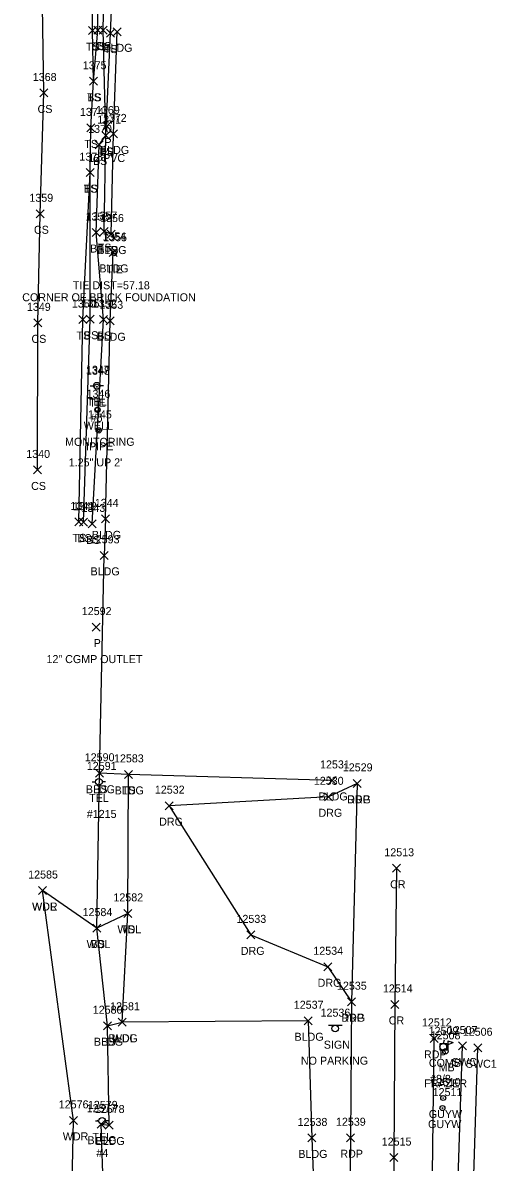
# Model space of a CAD drawing. Extents: x 1769141 to 1770817, y 735471 to 742405.
# Drawn here: x 1770172.1 to 1770290.5, y 741211.2 to 741496 of the extents above; entities that cross this region are included whole.
import ezdxf

# ---------------------------------------------------------------- set-up
doc = ezdxf.new("R2010")
doc.units = 0
for name, color, linetype in [('C_A', 7, 'Continuous'), ('C_C', 7, 'Continuous'), ('C_I', 7, 'Continuous'), ('CBP', 7, 'Continuous'), ('D_A', 7, 'Continuous'), ('D_C', 7, 'Continuous'), ('D_I', 7, 'Continuous'), ('D_TIC', 7, 'Continuous'), ('L_A', 7, 'Continuous'), ('L_C', 7, 'Continuous'), ('L_I', 7, 'Continuous'), ('L_TIC', 7, 'Continuous'), ('LAWA', 7, 'Continuous'), ('LBC', 7, 'Continuous'), ('LELB', 7, 'Continuous'), ('LMB', 7, 'Continuous'), ('M_A', 7, 'Continuous'), ('M_C', 7, 'Continuous'), ('M_I', 7, 'Continuous'), ('MPIP', 7, 'Continuous'), ('P_A', 7, 'Continuous'), ('P_I', 7, 'Continuous'), ('P_TIC', 7, 'Continuous'), ('PET', 7, 'Continuous'), ('PRC', 7, 'Continuous'), ('R_A', 7, 'Continuous'), ('R_I', 7, 'Continuous'), ('R_TIC', 7, 'Continuous'), ('RDG', 7, 'Continuous'), ('RSW', 7, 'Continuous'), ('S_A', 7, 'Continuous'), ('S_C', 7, 'Continuous'), ('S_I', 7, 'Continuous'), ('SSGN', 7, 'Continuous'), ('U_A', 7, 'Continuous'), ('U_C', 7, 'Continuous'), ('U_I', 7, 'Continuous'), ('UP', 7, 'Continuous'), ('UPGW', 7, 'Continuous'), ('UWW', 7, 'Continuous')]:
    doc.layers.add(name, color=color, linetype=linetype)

msp = doc.modelspace()

# ---------------------------------------------------------------- linework, layer by layer
at = {"layer": 'CBP'}
for centre, radius in [((1770194.94, 741438.44), 0.625), ((1770194.94, 741438.44), 0.0833), ((1770190.65, 741405.07), 0.625), ((1770190.65, 741405.07), 0.0833)]:
    msp.add_circle(centre, radius, dxfattribs=at)
at = {"layer": 'D_TIC'}
for points in [[(1770192.18, 741469.25), (1770194.18, 741471.25)], [(1770194.18, 741469.25), (1770192.18, 741471.25)], [(1770189.48, 741344), (1770191.48, 741346)], [(1770191.48, 741344), (1770189.48, 741346)]]:
    msp.add_lwpolyline(points, dxfattribs=at)
at = {"layer": 'L_TIC'}
for points in [[(1770188.54, 741493.09), (1770190.54, 741495.09)], [(1770190.54, 741493.09), (1770188.54, 741495.09)], [(1770189.88, 741493.18), (1770191.88, 741495.18)], [(1770191.88, 741493.18), (1770189.88, 741495.18)], [(1770191.23, 741493.22), (1770193.23, 741495.22)], [(1770193.23, 741493.22), (1770191.23, 741495.22)], [(1770193.03, 741492.48), (1770195.03, 741494.48)], [(1770195.03, 741492.48), (1770193.03, 741494.48)], [(1770194.7, 741492.79), (1770196.7, 741494.79)], [(1770196.7, 741492.79), (1770194.7, 741494.79)], [(1770188.82, 741480.43), (1770190.82, 741482.43)], [(1770190.82, 741480.43), (1770188.82, 741482.43)], [(1770188.82, 741480.43), (1770190.82, 741482.43)], [(1770190.82, 741480.43), (1770188.82, 741482.43)], [(1770176.38, 741477.5), (1770178.38, 741479.5)], [(1770178.38, 741477.5), (1770176.38, 741479.5)], [(1770188.13, 741468.78), (1770190.13, 741470.78)], [(1770190.13, 741468.78), (1770188.13, 741470.78)], [(1770191.9, 741466.86), (1770193.9, 741468.86)], [(1770193.9, 741466.86), (1770191.9, 741468.86)], [(1770191.9, 741466.86), (1770193.9, 741468.86)], [(1770193.9, 741466.86), (1770191.9, 741468.86)], [(1770193.86, 741467.27), (1770195.86, 741469.27)], [(1770195.86, 741467.27), (1770193.86, 741469.27)], [(1770190.25, 741464.52), (1770192.25, 741466.52)], [(1770192.25, 741464.52), (1770190.25, 741466.52)], [(1770187.97, 741457.59), (1770189.97, 741459.59)], [(1770189.97, 741457.59), (1770187.97, 741459.59)], [(1770187.97, 741457.59), (1770189.97, 741459.59)], [(1770189.97, 741457.59), (1770187.97, 741459.59)], [(1770175.49, 741447.31), (1770177.49, 741449.31)], [(1770177.49, 741447.31), (1770175.49, 741449.31)], [(1770189.52, 741442.62), (1770191.52, 741444.62)], [(1770191.52, 741442.62), (1770189.52, 741444.62)], [(1770191.49, 741442.85), (1770193.49, 741444.85)], [(1770193.49, 741442.85), (1770191.49, 741444.85)], [(1770193.21, 741442.24), (1770195.21, 741444.24)], [(1770195.21, 741442.24), (1770193.21, 741444.24)], [(1770193.21, 741442.24), (1770195.21, 741444.24)], [(1770195.21, 741442.24), (1770193.21, 741444.24)], [(1770193.7, 741437.66), (1770195.7, 741439.66)], [(1770195.7, 741437.66), (1770193.7, 741439.66)], [(1770186.18, 741420.88), (1770188.18, 741422.88)], [(1770188.18, 741420.88), (1770186.18, 741422.88)], [(1770187.99, 741420.95), (1770189.99, 741422.95)], [(1770189.99, 741420.95), (1770187.99, 741422.95)], [(1770191.33, 741420.87), (1770193.33, 741422.87)], [(1770193.33, 741420.87), (1770191.33, 741422.87)], [(1770192.99, 741420.56), (1770194.99, 741422.56)], [(1770194.99, 741420.56), (1770192.99, 741422.56)], [(1770174.87, 741420.05), (1770176.87, 741422.05)], [(1770176.87, 741420.05), (1770174.87, 741422.05)], [(1770174.78, 741383.28), (1770176.78, 741385.28)], [(1770176.78, 741383.28), (1770174.78, 741385.28)], [(1770185.17, 741370.3), (1770187.17, 741372.3)], [(1770187.17, 741370.3), (1770185.17, 741372.3)], [(1770186.36, 741370.22), (1770188.36, 741372.22)], [(1770188.36, 741370.22), (1770186.36, 741372.22)], [(1770188.51, 741369.79), (1770190.51, 741371.79)], [(1770190.51, 741369.79), (1770188.51, 741371.79)], [(1770191.84, 741371.05), (1770193.84, 741373.05)], [(1770193.84, 741371.05), (1770191.84, 741373.05)], [(1770191.49, 741361.93), (1770193.49, 741363.93)], [(1770193.49, 741361.93), (1770191.49, 741363.93)], [(1770190.3, 741307.46), (1770192.3, 741309.46)], [(1770192.3, 741307.46), (1770190.3, 741309.46)], [(1770190.3, 741307.46), (1770192.3, 741309.46)], [(1770192.3, 741307.46), (1770190.3, 741309.46)], [(1770197.53, 741307.18), (1770199.53, 741309.18)], [(1770199.53, 741307.18), (1770197.53, 741309.18)], [(1770197.53, 741307.18), (1770199.53, 741309.18)], [(1770199.53, 741307.18), (1770197.53, 741309.18)], [(1770248.5, 741305.67), (1770250.5, 741307.67)], [(1770250.5, 741305.67), (1770248.5, 741307.67)], [(1770176.08, 741278.15), (1770178.08, 741280.15)], [(1770178.08, 741278.15), (1770176.08, 741280.15)], [(1770176.08, 741278.15), (1770178.08, 741280.15)], [(1770178.08, 741278.15), (1770176.08, 741280.15)], [(1770197.39, 741272.44), (1770199.39, 741274.44)], [(1770199.39, 741272.44), (1770197.39, 741274.44)], [(1770197.39, 741272.44), (1770199.39, 741274.44)], [(1770199.39, 741272.44), (1770197.39, 741274.44)], [(1770189.68, 741268.76), (1770191.68, 741270.76)], [(1770191.68, 741268.76), (1770189.68, 741270.76)], [(1770189.68, 741268.76), (1770191.68, 741270.76)], [(1770191.68, 741268.76), (1770189.68, 741270.76)], [(1770192.32, 741244.36), (1770194.32, 741246.36)], [(1770194.32, 741244.36), (1770192.32, 741246.36)], [(1770192.32, 741244.36), (1770194.32, 741246.36)], [(1770194.32, 741244.36), (1770192.32, 741246.36)], [(1770196.01, 741245.22), (1770198.01, 741247.22)], [(1770198.01, 741245.22), (1770196.01, 741247.22)], [(1770196.01, 741245.22), (1770198.01, 741247.22)], [(1770198.01, 741245.22), (1770196.01, 741247.22)], [(1770196.01, 741245.22), (1770198.01, 741247.22)], [(1770198.01, 741245.22), (1770196.01, 741247.22)], [(1770242.49, 741245.6), (1770244.49, 741247.6)], [(1770244.49, 741245.6), (1770242.49, 741247.6)], [(1770242.49, 741245.6), (1770244.49, 741247.6)], [(1770244.49, 741245.6), (1770242.49, 741247.6)], [(1770183.78, 741220.7), (1770185.78, 741222.7)], [(1770185.78, 741220.7), (1770183.78, 741222.7)], [(1770190.71, 741219.75), (1770192.71, 741221.75)], [(1770192.71, 741219.75), (1770190.71, 741221.75)], [(1770192.74, 741219.54), (1770194.74, 741221.54)], [(1770194.74, 741219.54), (1770192.74, 741221.54)], [(1770243.45, 741216.31), (1770245.45, 741218.31)], [(1770245.45, 741216.31), (1770243.45, 741218.31)]]:
    msp.add_lwpolyline(points, dxfattribs=at)
at = {"layer": 'LAWA'}
for points in [[(1770187.61, 741151.31), (1770184.04, 741186.63), (1770184.78, 741221.7), (1770177.08, 741279.15)], [(1770197.01, 741246.22), (1770198.39, 741273.44), (1770190.68, 741269.76), (1770177.08, 741279.15)]]:
    msp.add_lwpolyline(points, dxfattribs=at)
at = {"layer": 'LBC'}
for points in [[(1770194.21, 741443.24), (1770194.86, 741468.27), (1770195.7, 741493.79)], [(1770192.84, 741372.05), (1770193.99, 741421.56), (1770194.7, 741438.66)], [(1770192.84, 741372.05), (1770192.49, 741362.93)], [(1770249.5, 741306.67), (1770198.53, 741308.18), (1770191.3, 741308.46), (1770192.49, 741362.93)], [(1770218.24, 741153.48), (1770194.84, 741152.55), (1770193.62, 741152.51), (1770192.9, 741186.4), (1770191.71, 741220.75), (1770193.74, 741220.54), (1770193.32, 741245.36), (1770197.01, 741246.22)], [(1770243.49, 741246.6), (1770197.01, 741246.22)], [(1770243.49, 741246.6), (1770244.45, 741217.31), (1770246.14, 741171.01)]]:
    msp.add_lwpolyline(points, dxfattribs=at)
at = {"layer": 'LELB'}
for points in [[(1770189.82, 741481.43), (1770190.88, 741494.18), (1770191.42, 741543.22), (1770190.92, 741598.66), (1770192.66, 741636.32), (1770194.58, 741652.38), (1770196.84, 741676.51), (1770200.25, 741721.67), (1770205.66, 741764.05), (1770211.04, 741807.24), (1770214.71, 741843.41), (1770218.13, 741875.72), (1770220.67, 741890.47)], [(1770189.51, 741370.79), (1770192.33, 741421.87), (1770190.52, 741443.62), (1770191.25, 741465.52), (1770192.9, 741467.86), (1770192.23, 741494.22), (1770193.26, 741543.26), (1770192.21, 741598.2), (1770194.88, 741636.38), (1770196.63, 741652), (1770198.6, 741676.72), (1770202.3, 741721.55), (1770209.33, 741763.66), (1770214.61, 741807.75), (1770219.97, 741843.04), (1770223.09, 741876.08), (1770226.05, 741889.39), (1770243.39, 741887.35), (1770251.84, 741882.91)], [(1770186.17, 741371.3), (1770187.18, 741421.88), (1770188.97, 741458.59), (1770189.13, 741469.78), (1770189.82, 741481.43), (1770189.54, 741494.09), (1770189.26, 741543.13), (1770188.59, 741598.72), (1770190.44, 741636.22), (1770191.59, 741652.63)], [(1770194.21, 741443.24), (1770192.49, 741443.85), (1770192.9, 741467.86), (1770194.03, 741493.48), (1770196.24, 741542.72), (1770196.16, 741599.27), (1770199.91, 741635.96), (1770200.67, 741651.18)], [(1770175.78, 741384.28), (1770175.87, 741421.05), (1770176.49, 741448.31), (1770177.38, 741478.5), (1770176.41, 741543.71), (1770182.37, 741598.6), (1770182.53, 741636.98)], [(1770187.36, 741371.22), (1770188.99, 741421.95), (1770188.97, 741458.59)], [(1770193.32, 741245.36), (1770190.68, 741269.76), (1770191.3, 741308.46)], [(1770198.39, 741273.44), (1770198.53, 741308.18)]]:
    msp.add_lwpolyline(points, dxfattribs=at)
at = {"layer": 'LMB'}
for p, q in [((1770278.46, 741241.56), (1770279.76, 741241.18)), ((1770278.47, 741238.97), (1770278.47, 741241.57)), ((1770278.47, 741240.66), (1770279.75, 741241.17)), ((1770277.81, 741238.96), (1770277.81, 741238.96))]:
    msp.add_line(p, q, dxfattribs=at)
msp.add_circle((1770277.81, 741238.96), 0.656, dxfattribs=at)
at = {"layer": 'MPIP'}
msp.add_lwpolyline([(1770191.46, 741394.17), (1770191.13, 741394.5), (1770190.8, 741394.17), (1770191.13, 741393.84)], close=True, dxfattribs=at)
msp.add_circle((1770191.13, 741394.17), 0.667, dxfattribs=at)
at = {"layer": 'P_TIC'}
for points in [[(1770254.76, 741304.94), (1770256.76, 741306.94)], [(1770256.76, 741304.94), (1770254.76, 741306.94)], [(1770264.56, 741283.71), (1770266.56, 741285.71)], [(1770266.56, 741283.71), (1770264.56, 741285.71)], [(1770253.29, 741250.36), (1770255.29, 741252.36)], [(1770255.29, 741250.36), (1770253.29, 741252.36)], [(1770264.2, 741249.68), (1770266.2, 741251.68)], [(1770266.2, 741249.68), (1770264.2, 741251.68)], [(1770273.97, 741241.19), (1770275.97, 741243.19)], [(1770275.97, 741241.19), (1770273.97, 741243.19)], [(1770253.05, 741216.36), (1770255.05, 741218.36)], [(1770255.05, 741216.36), (1770253.05, 741218.36)], [(1770263.91, 741211.4), (1770265.91, 741213.4)], [(1770265.91, 741211.4), (1770263.91, 741213.4)]]:
    msp.add_lwpolyline(points, dxfattribs=at)
at = {"layer": 'PET'}
for points in [[(1770255.76, 741305.94), (1770254.29, 741251.36), (1770254.05, 741217.36), (1770253.59, 741164.42), (1770250.51, 741146.51), (1770240.62, 741135.92), (1770219.62, 741128.16)], [(1770274.45, 741175.13), (1770274.38, 741194.74), (1770274.97, 741242.19)]]:
    msp.add_lwpolyline(points, dxfattribs=at)
at = {"layer": 'PRC'}
msp.add_lwpolyline([(1770265.56, 741284.71), (1770265.2, 741250.68), (1770264.91, 741212.4), (1770264.73, 741176.65), (1770264.85, 741146.95)], dxfattribs=at)
at = {"layer": 'R_TIC'}
for points in [[(1770254.76, 741304.94), (1770256.76, 741306.94)], [(1770256.76, 741304.94), (1770254.76, 741306.94)], [(1770247.6, 741301.58), (1770249.6, 741303.58)], [(1770249.6, 741301.58), (1770247.6, 741303.58)], [(1770207.75, 741299.36), (1770209.75, 741301.36)], [(1770209.75, 741299.36), (1770207.75, 741301.36)], [(1770228.16, 741267.07), (1770230.16, 741269.07)], [(1770230.16, 741267.07), (1770228.16, 741269.07)], [(1770247.38, 741259.09), (1770249.38, 741261.09)], [(1770249.38, 741259.09), (1770247.38, 741261.09)], [(1770253.29, 741250.36), (1770255.29, 741252.36)], [(1770255.29, 741250.36), (1770253.29, 741252.36)], [(1770281.07, 741239.29), (1770283.07, 741241.29)], [(1770283.07, 741239.29), (1770281.07, 741241.29)], [(1770284.88, 741238.85), (1770286.88, 741240.85)], [(1770286.88, 741238.85), (1770284.88, 741240.85)]]:
    msp.add_lwpolyline(points, dxfattribs=at)
at = {"layer": 'RDG'}
msp.add_lwpolyline([(1770255.76, 741305.94), (1770248.6, 741302.58), (1770208.75, 741300.36), (1770229.16, 741268.07), (1770248.38, 741260.09), (1770254.29, 741251.36)], dxfattribs=at)
at = {"layer": 'RSW'}
for points in [[(1770280.6, 741194.6), (1770282.07, 741240.29)], [(1770284.47, 741194.72), (1770285.88, 741239.85)]]:
    msp.add_lwpolyline(points, dxfattribs=at)
at = {"layer": 'SSGN'}
for p, q in [((1770248.62, 741245.48), (1770251.96, 741245.48)), ((1770250.27, 741244.64), (1770250.27, 741244.64))]:
    msp.add_line(p, q, dxfattribs=at)
msp.add_circle((1770250.27, 741244.64), 0.833, dxfattribs=at)
at = {"layer": 'UP'}
for p, q in [((1770188.97, 741405.34), (1770189.8, 741405.34)), ((1770190.63, 741405.34), (1770190.63, 741405.34)), ((1770192.3, 741405.34), (1770191.47, 741405.34)), ((1770191.47, 741405.34), (1770191.47, 741405.34)), ((1770192.3, 741405.34), (1770192.3, 741405.34)), ((1770189.52, 741306.29), (1770190.34, 741306.29)), ((1770191.18, 741306.3), (1770191.18, 741306.3)), ((1770192.84, 741306.3), (1770192.01, 741306.3)), ((1770192.01, 741306.3), (1770192.01, 741306.3)), ((1770192.84, 741306.3), (1770192.84, 741306.3)), ((1770276.46, 741239.24), (1770276.46, 741240.9)), ((1770276.46, 741240.9), (1770278.13, 741240.9)), ((1770277.54, 741241.74), (1770277.29, 741240.9)), ((1770278.13, 741240.9), (1770278.13, 741239.24)), ((1770278.13, 741239.24), (1770276.46, 741239.24)), ((1770277.04, 741238.4), (1770277.29, 741239.24)), ((1770277.29, 741240.07), (1770277.29, 741240.07)), ((1770190.36, 741221.57), (1770191.18, 741221.57)), ((1770192.01, 741221.57), (1770192.01, 741221.57)), ((1770193.68, 741221.57), (1770192.85, 741221.57)), ((1770192.85, 741221.57), (1770192.85, 741221.57)), ((1770193.68, 741221.57), (1770193.68, 741221.57))]:
    msp.add_line(p, q, dxfattribs=at)
for centre in [(1770190.63, 741405.34), (1770191.18, 741306.3), (1770277.29, 741240.07), (1770192.01, 741221.57)]:
    msp.add_circle(centre, 0.833, dxfattribs=at)
at = {"layer": 'UPGW'}
for centre, radius in [((1770277.28, 741227.29), 0.625), ((1770277.28, 741227.29), 0.0833), ((1770277.08, 741224.77), 0.625), ((1770277.08, 741224.77), 0.0833)]:
    msp.add_circle(centre, radius, dxfattribs=at)
at = {"layer": 'UWW'}
for radius in [0.667, 0.625, 0.583, 0.542]:
    msp.add_circle((1770190.82, 741399.31), radius, dxfattribs=at)

# ---------------------------------------------------------------- texts
at = {"layer": 'C_A'}
for p in [(1770193.02, 741433.44), (1770188.73, 741400.07)]:
    msp.add_text('TIE', height=2, dxfattribs=at).set_placement(p)
at = {"layer": 'C_C'}
for s, p in [('TIE DIST=57.18', (1770184.64, 741429.44)), ('CORNER OF BRICK FOUNDATION', (1770172, 741426.44))]:
    msp.add_text(s, height=2, dxfattribs=at).set_placement(p)
at = {"layer": 'C_I'}
for s, p in [('1355', (1770192.24, 741441.44)), ('1348', (1770187.96, 741408.07))]:
    msp.add_text(s, height=2, dxfattribs=at).set_placement(p)
at = {"layer": 'D_A'}
for p in [(1770192.56, 741465.25), (1770189.86, 741340)]:
    msp.add_text('P', height=2, dxfattribs=at).set_placement(p)
at = {"layer": 'D_C'}
for s, p in [('12 PVC', (1770188.51, 741461.25)), ('12" CGMP OUTLET', (1770178.07, 741336))]:
    msp.add_text(s, height=2, dxfattribs=at).set_placement(p)
at = {"layer": 'D_I'}
for s, p in [('1369', (1770190.43, 741473.25)), ('12592', (1770186.89, 741348))]:
    msp.add_text(s, height=2, dxfattribs=at).set_placement(p)
at = {"layer": 'L_A'}
for s, p in [('TS', (1770187.95, 741489.09)), ('BS', (1770189.32, 741489.18)), ('BS', (1770190.67, 741489.22)), ('TS', (1770192.44, 741488.48)), ('BLDG', (1770192.29, 741488.79)), ('TS', (1770188.23, 741476.43)), ('BS', (1770188.27, 741476.43)), ('CS', (1770175.83, 741473.5)), ('TS', (1770187.54, 741464.78)), ('BLDG', (1770191.45, 741463.27)), ('BS', (1770189.7, 741460.52)), ('TS', (1770191.31, 741462.86)), ('BS', (1770191.34, 741462.86)), ('TS', (1770187.38, 741453.59)), ('BS', (1770187.41, 741453.59)), ('CS', (1770174.93, 741443.31)), ('BS', (1770188.96, 741438.62)), ('TS', (1770190.9, 741438.85)), ('BLDG', (1770190.8, 741438.24)), ('TS', (1770192.62, 741438.24)), ('BLDG', (1770191.29, 741433.66)), ('CS', (1770174.31, 741416.05)), ('TS', (1770185.59, 741416.88)), ('BS', (1770187.43, 741416.95)), ('BLDG', (1770190.58, 741416.56)), ('BS', (1770190.77, 741416.87)), ('CS', (1770174.22, 741379.28)), ('BLDG', (1770189.43, 741367.05)), ('TS', (1770184.58, 741366.3)), ('BS', (1770185.8, 741366.22)), ('BS', (1770187.95, 741365.79)), ('BLDG', (1770189.08, 741357.93)), ('BLDG', (1770187.9, 741303.46)), ('BS', (1770189.75, 741303.46)), ('BLDG', (1770195.12, 741303.18)), ('TS', (1770196.94, 741303.18)), ('BLDG', (1770246.09, 741301.67)), ('WDR', (1770174.44, 741274.15)), ('WDL', (1770174.49, 741274.15)), ('WDL', (1770195.81, 741268.44)), ('TS', (1770196.8, 741268.44)), ('WDL', (1770188.1, 741264.76)), ('BS', (1770189.12, 741264.76)), ('BLDG', (1770193.6, 741241.22)), ('BLDG', (1770193.6, 741241.22)), ('WDL', (1770194.42, 741241.22)), ('BLDG', (1770240.08, 741241.6)), ('BLDG', (1770240.08, 741241.6)), ('BLDG', (1770189.91, 741240.36)), ('BS', (1770191.76, 741240.36)), ('MB', (1770276.12, 741233.96)), ('WDR', (1770182.14, 741216.7)), ('BLDG', (1770188.3, 741215.75)), ('BLDG', (1770190.33, 741215.54)), ('BLDG', (1770241.04, 741212.31))]:
    msp.add_text(s, height=2, dxfattribs=at).set_placement(p)
at = {"layer": 'L_C'}
msp.add_text('FRAZER', height=2, dxfattribs=at).set_placement((1770272.53, 741229.96))
at = {"layer": 'L_I'}
for s, p in [('1375', (1770187.13, 741484.43)), ('1375', (1770187.13, 741484.43)), ('1368', (1770174.64, 741481.5)), ('1374', (1770186.43, 741472.78)), ('1371', (1770190.77, 741470.86)), ('1371', (1770190.77, 741470.86)), ('1372', (1770192.16, 741471.27)), ('1370', (1770188.48, 741468.52)), ('1373', (1770186.28, 741461.59)), ('1373', (1770186.28, 741461.59)), ('1359', (1770173.78, 741451.31)), ('1358', (1770187.83, 741446.62)), ('1357', (1770189.8, 741446.85)), ('1356', (1770191.47, 741446.24)), ('1356', (1770191.47, 741446.24)), ('1354', (1770192.01, 741441.66)), ('1349', (1770173.17, 741424.05)), ('1350', (1770184.4, 741424.88)), ('1351', (1770186.86, 741424.95)), ('1352', (1770189.64, 741424.87)), ('1353', (1770191.29, 741424.56)), ('1340', (1770173, 741387.28)), ('1344', (1770190.15, 741375.05)), ('1341', (1770184.05, 741374.3)), ('1342', (1770184.67, 741374.22)), ('1343', (1770186.82, 741373.79)), ('12593', (1770188.89, 741365.93)), ('12590', (1770187.63, 741311.46)), ('12590', (1770187.63, 741311.46)), ('12583', (1770194.94, 741311.18)), ('12583', (1770194.94, 741311.18)), ('12531', (1770246.47, 741309.67)), ('12585', (1770173.49, 741282.15)), ('12585', (1770173.49, 741282.15)), ('12582', (1770194.8, 741276.44)), ('12582', (1770194.8, 741276.44)), ('12584', (1770187.09, 741272.76)), ('12584', (1770187.09, 741272.76)), ('12537', (1770239.9, 741249.6)), ('12537', (1770239.9, 741249.6)), ('12580', (1770189.64, 741248.36)), ('12580', (1770189.64, 741248.36)), ('12581', (1770193.98, 741249.22)), ('12581', (1770193.98, 741249.22)), ('12581', (1770193.98, 741249.22)), ('12508', (1770274.14, 741241.96)), ('12576', (1770181.14, 741224.7)), ('12577', (1770188.12, 741223.75)), ('12578', (1770190.15, 741223.54)), ('12538', (1770240.86, 741220.31))]:
    msp.add_text(s, height=2, dxfattribs=at).set_placement(p)
at = {"layer": 'M_A'}
msp.add_text('IPIPE', height=2, dxfattribs=at).set_placement((1770187.96, 741389.17))
at = {"layer": 'M_C'}
msp.add_text('1.25" UP 2\'', height=2, dxfattribs=at).set_placement((1770183.63, 741385.17))
at = {"layer": 'M_I'}
msp.add_text('1345', height=2, dxfattribs=at).set_placement((1770188.44, 741397.17))
at = {"layer": 'P_A'}
for s, p in [('RDP', (1770253.25, 741300.94)), ('CR', (1770263.99, 741279.71)), ('RDP', (1770251.78, 741246.36)), ('CR', (1770263.64, 741245.68)), ('RDP', (1770272.45, 741237.19)), ('RDP', (1770251.54, 741212.36))]:
    msp.add_text(s, height=2, dxfattribs=at).set_placement(p)
at = {"layer": 'P_I'}
for s, p in [('12529', (1770252.16, 741308.94)), ('12513', (1770262.54, 741287.71)), ('12535', (1770250.7, 741254.36)), ('12514', (1770262.18, 741253.68)), ('12512', (1770271.94, 741245.19)), ('12539', (1770250.45, 741220.36)), ('12515', (1770261.89, 741215.4))]:
    msp.add_text(s, height=2, dxfattribs=at).set_placement(p)
at = {"layer": 'R_A'}
for s, p in [('DRG', (1770253.25, 741300.94)), ('DRG', (1770206.24, 741295.36)), ('DRG', (1770246.08, 741297.58)), ('DRG', (1770226.65, 741263.07)), ('DRG', (1770245.86, 741255.09)), ('DRG', (1770251.78, 741246.36)), ('SWC', (1770279.44, 741235.29)), ('SWC1', (1770282.92, 741234.85))]:
    msp.add_text(s, height=2, dxfattribs=at).set_placement(p)
at = {"layer": 'R_I'}
for s, p in [('12529', (1770252.16, 741308.94)), ('12530', (1770244.92, 741305.58)), ('12532', (1770205.16, 741303.36)), ('12533', (1770225.57, 741271.07)), ('12534', (1770244.79, 741263.09)), ('12535', (1770250.7, 741254.36)), ('12507', (1770278.4, 741243.29)), ('12506', (1770282.16, 741242.85))]:
    msp.add_text(s, height=2, dxfattribs=at).set_placement(p)
at = {"layer": 'S_A'}
msp.add_text('SIGN', height=2, dxfattribs=at).set_placement((1770247.41, 741239.62))
at = {"layer": 'S_C'}
msp.add_text('NO PARKING', height=2, dxfattribs=at).set_placement((1770241.69, 741235.62))
at = {"layer": 'S_I'}
msp.add_text('12536', height=2, dxfattribs=at).set_placement((1770246.6, 741247.62))
at = {"layer": 'U_A'}
for s, p in [('TEL', (1770188.19, 741400.34)), ('WELL', (1770187.39, 741394.31)), ('TEL', (1770188.74, 741301.3)), ('COMB', (1770273.68, 741235.07)), ('GUYW', (1770273.67, 741222.29)), ('GUYW', (1770273.47, 741219.77)), ('TEL', (1770189.57, 741216.57))]:
    msp.add_text(s, height=2, dxfattribs=at).set_placement(p)
at = {"layer": 'U_C'}
for s, p in [('#6', (1770189.11, 741396.34)), ('MONITORING', (1770182.71, 741390.31)), ('#1215', (1770188.15, 741297.3)), ('#8/8', (1770273.96, 741231.07)), ('#4', (1770190.55, 741212.57))]:
    msp.add_text(s, height=2, dxfattribs=at).set_placement(p)
at = {"layer": 'U_I'}
for s, p in [('1347', (1770187.94, 741408.34)), ('1346', (1770188.08, 741402.31)), ('12591', (1770188.15, 741309.3)), ('12509', (1770273.62, 741243.07)), ('12510', (1770274.17, 741230.29)), ('12511', (1770274.62, 741227.77)), ('12579', (1770188.42, 741224.57))]:
    msp.add_text(s, height=2, dxfattribs=at).set_placement(p)

doc.saveas('drawing.dxf')
